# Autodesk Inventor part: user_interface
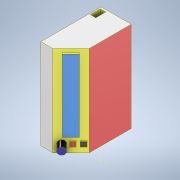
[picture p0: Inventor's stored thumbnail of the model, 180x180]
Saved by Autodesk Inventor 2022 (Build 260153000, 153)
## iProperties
Created: 2021-06
Part Number: user_interface
Material: PBT Plastic
Document SubType Name: Modeling
Designer: Chimms
Density: 1.31 g/cm^3
Appearance: Smooth - Yellow
Author: Chimms
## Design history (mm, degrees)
sketch "Sketch1"
  geometry: L1 (0, 0)-(50, 0); L2 (50, 0)-(50, 150); L3 (50, 150)-(0, 150); L4 (0, 150)-(0, 0)
  constraints: 8 end point, 2 parallel, 1 horizontal, 1 perpendicular
  dimensions: "d0" = 50 distance of L3.end L2.end; "d1" = 150 distance of L2.end L1.end
extrude "Extrusion1" new body sketch "Sketch1" distance "d2" = 100; taper "d3" = 0 deg
chamfer "Chamfer1" distance "d4" = 30; stored, may be unused: second distance "d5" = 2, angle "d6" = 45 deg
sketch "Sketch2"
  geometry: L1 (10.938, 144.256)-(30.938, 144.256); L2 (30.938, 144.256)-(30.938, 24.256); L3 (30.938, 24.256)-(10.938, 24.256); L4 (10.938, 24.256)-(10.938, 144.256); 1 further point
  constraints: 8 end point, 2 parallel, 1 horizontal, 1 perpendicular
  dimensions: "d7" = 20 distance of L2.end L3.end; "d8" = 120 distance of L1.end L2.end
extrude "Extrusion2" join sketch "Sketch2" distance "d9" = 3; taper "d10" = 0 deg
sketch "Sketch3"
  geometry: L1 (31.452, 9.074)-(23.452, 9.074); L2 (23.452, 9.074)-(23.452, 17.074); L3 (23.452, 17.074)-(31.452, 17.074); L4 (31.452, 17.074)-(31.452, 9.074); C1 r 6 at (10.149, 13.019); 1 further point
  constraints: 8 end point, 2 parallel, 1 centre point, 1 horizontal, 1 perpendicular
  dimensions: "d11" = 12 diameter of C1; "d12" = 8 distance of L2.end L3.end; "d13" = 8 distance of L1.end L2.end
extrude "Extrusion3" join sketch "Sketch3" distance "d14" = 15; taper "d15" = 0 deg
sketch "Sketch4"
  geometry: 1 further point
sketch "Sketch6"
  geometry: C1 r 3.994 at (0, 0); 1 further point
  constraints: 1 centre point
sketch "Sketch7"
  geometry: L1 (2.328, -3.745)-(11.234, -3.745); L2 (11.234, -3.745)-(11.234, -20.139); L3 (11.234, -20.139)-(2.328, -20.139); L4 (2.328, -20.139)-(2.328, -3.745); 1 further point
  constraints: 8 end point, 2 parallel, 1 horizontal, 1 perpendicular
extrude "Extrusion5" cut sketch "Sketch7" distance "d23" = 8; taper "d24" = 0 deg
sketch "Sketch8"
  geometry: L1 (39.977, 17.774)-(31.977, 17.774); L2 (31.977, 17.774)-(31.977, 9.774); L3 (31.977, 9.774)-(39.977, 9.774); L4 (39.977, 9.774)-(39.977, 17.774); L5 (27.26, 17.774)-(19.26, 17.774); L6 (19.26, 17.774)-(19.26, 9.774); L7 (19.26, 9.774)-(27.26, 9.774); L8 (27.26, 9.774)-(27.26, 17.774); 1 further point
  constraints: 16 end point, 4 parallel, 2 horizontal, 2 perpendicular, 2 point on line
  dimensions: "d25" = 8 distance of L3.end L2.end; "d26" = 8 distance of L2.end L1.end; "d27" = 8 distance of L7.end L6.end
extrude "Extrusion6" join sketch "Sketch8" distance "d28" = 2; taper "d29" = 0 deg
body "Solid1"
